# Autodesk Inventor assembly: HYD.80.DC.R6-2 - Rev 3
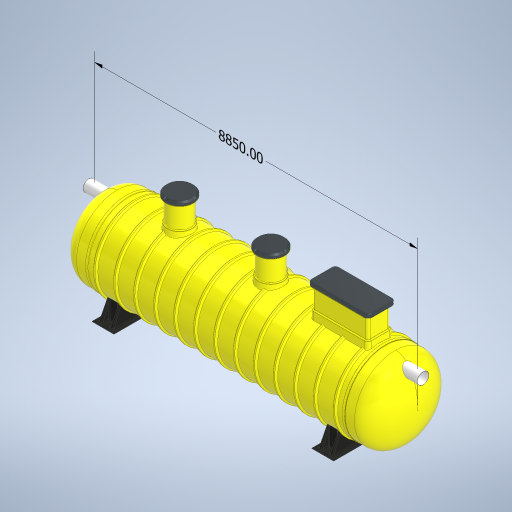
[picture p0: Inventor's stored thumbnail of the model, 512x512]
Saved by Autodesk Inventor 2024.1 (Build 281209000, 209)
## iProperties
Created: 2023-08
Part Number: HYD.80.DC.R6-2 - Rev 3
Document SubType Name: Assembly
Designer: macga
Author: macga
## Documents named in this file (44)
- D:\$ Protector Vault\Workspace\Automation Files\1. Protector Stardard Products\HydroProtectors\FAMILY\HYD.80 - Vernon\HYD.80.DC.R6-2 - Rev 3.iam
- D:\$ Protector Vault\Workspace\1. Protector Stardard Products\HydroProtectors\FAMILY\HORIZONTAL TANK - IPART\HORIZONTAL TANK - IPART.ipt
- D:\$ Protector Vault\Workspace\1. Protector Stardard Products\HydroProtectors\FAMILY\DOME - IPART\DOME - IPART.ipt
- D:\$ Protector Vault\Workspace\1. Protector Stardard Products\HydroProtectors\FAMILY\FOOT - IPART\FRP Foot - IPART.ipt
- D:\$ Protector Vault\Workspace\1. Protector Stardard Products\HydroProtectors\FAMILY\ACDTUBE - IPART\ACDTUBE - IPART.ipt
- D:\$ Protector Vault\Workspace\1. Protector Stardard Products\HydroProtectors\FAMILY\ACD FLOAT VALVE - IPART\ACD.FloatValve - IASSY.iam
- D:\$ Protector Vault\Workspace\1. Protector Stardard Products\HydroProtectors\FAMILY\SU.600Dia Manway Adaptor - IPART\SU.MWA.HS.6R - IPART.ipt
- D:\$ Protector Vault\Workspace\1. Protector Stardard Products\HydroProtectors\FAMILY\WIN.600mmDiaManwayRiser - IPART\600mmDia Manway Riser.ipt
- D:\$ Protector Vault\Workspace\1. Protector Stardard Products\HydroProtectors\Automation Files\600mmDia Manway Cover.ipt
- D:\$ Protector Vault\Workspace\1. Protector Stardard Products\HydroProtectors\FAMILY\OUTLET ELBOW - IPART\OUTLET ELBOW - IPART.ipt
- D:\$ Protector Vault\Workspace\1. Protector Stardard Products\HydroProtectors\Coalescer Guide Rail.ipt
- D:\$ Protector Vault\Workspace\1. Protector Stardard Products\HydroProtectors\ISO 4065 Pipe DN315x2.5xS63 - 1365.ipt
- D:\$ Protector Vault\Workspace\1. Protector Stardard Products\HydroProtectors\FAMILY\INLET PIPE ELBOW- IPART\INLET PIPE ELBOW- IPART\InletPipeElbow.300D.ipt
- D:\$ Protector Vault\Workspace\1. Protector Stardard Products\HydroProtectors\FAMILY\INLET PIPE ELBOW- IPART\INLET PIPE ELBOW- IPART.ipt
- D:\$ Protector Vault\Workspace\1. Protector Stardard Products\HydroProtectors\Upper Guide Rai Braket.ipt
- D:\$ Protector Vault\Workspace\1. Protector Stardard Products\Standard Components\Flanged Vent.ipt
- D:\$ Protector Vault\Workspace\1. Protector Stardard Products\HydroProtectors\HYD Oil Probe\Oil Probe Assembly.iam
- D:\$ Protector Vault\Workspace\1. Protector Stardard Products\HydroProtectors\FAMILY\DOME - IPART\DOME - IPART\SU.DOME.2200-10.ipt
- D:\$ Protector Vault\Workspace\1. Protector Stardard Products\HydroProtectors\FAMILY\FOOT - IPART\FRP Foot - IPART\SU.HS.FOOT.2200.ipt
- D:\$ Protector Vault\Workspace\1. Protector Stardard Products\HydroProtectors\FAMILY\HYD.BAFFLE - IPART\SU.BAFFLE.2200\SU.BAFFLE.2200.ipt
- D:\$ Protector Vault\Workspace\1. Protector Stardard Products\HydroProtectors\FAMILY\HYD.BAFFLE - IPART\SU.BAFFLE.2200.ipt
- D:\$ Protector Vault\Workspace\1. Protector Stardard Products\HydroProtectors\FAMILY\SU.600Dia Manway Adaptor - IPART\Horizontal 600mmDia Manway Adaptor (FLANGED) SU.MWA.HS.6R-1850-1850\SU.MWA.HS.6R-2200.ipt
- D:\$ Protector Vault\Workspace\1. Protector Stardard Products\HydroProtectors\FAMILY\ACD Base - IPART\SU.ACDBASE.2200\SU.ACDBASE.2200-450ACDFV.ipt
- D:\$ Protector Vault\Workspace\1. Protector Stardard Products\HydroProtectors\FAMILY\ACD Base - IPART\SU.ACDBASE.2200.ipt
- D:\$ Protector Vault\Workspace\1. Protector Stardard Products\HydroProtectors\HYD.70 300 Outlet Vertical.ipt
- D:\$ Protector Vault\Workspace\1. Protector Stardard Products\HydroProtectors\FAMILY\ACDTUBE - IPART\ACDTUBE - IPART\ACDTUBE.450-1846.ipt
- D:\$ Protector Vault\Workspace\1. Protector Stardard Products\HydroProtectors\FAMILY\ACD FLOAT VALVE - IPART\ACD.FloatValve - IASSY\ACD.FVALVE.450.ASSY.iam
- D:\$ Protector Vault\Workspace\1. Protector Stardard Products\HydroProtectors\FAMILY\OUTLET ELBOW - IPART\OUTLET ELBOW - IPART\OutletPipeElbow.300D-100DCoupling.ipt
- D:\$ Protector Vault\Workspace\1. Protector Stardard Products\Xtremeprotector\Vault\Chain.ipt
- D:\$ Protector Vault\Workspace\1. Protector Stardard Products\Xtremeprotector\Vault\Lifting Eye.ipt
- D:\$ Protector Vault\Workspace\1. Protector Stardard Products\HydroProtectors\FAMILY\Coalescer Guide Rail-018.ipt
- D:\$ Protector Vault\Workspace\1. Protector Stardard Products\HydroProtectors\FAMILY\Coalescer Guide Rail-019.ipt
- D:\$ Protector Vault\Workspace\Automation Files\1. Protector Stardard Products\HydroProtectors\FAMILY\CF.BASE - IPART\CF BASE DUAL - IPART\SU.CFBASE.2200.DUAL.ipt
- D:\$ Protector Vault\Workspace\1. Protector Stardard Products\HydroProtectors\FAMILY\HORIZONTAL TANK - IPART\HORIZONTAL TANK - IPART\WIN.HB.2200x7090L-10.ipt
- D:\$ Protector Vault\Workspace\Automation Files\1. Protector Stardard Products\HydroProtectors\FAMILY\CF.BASE - IPART\CF BASE DUAL - IPART\SU.CFBASE.2200.DUAL\SU.CFBASE.2200.B1.2-R6-OP.300.ipt
- D:\$ Protector Vault\Workspace\1. Protector Stardard Products\HydroProtectors\FAMILY\COALESCER FILTER - IPART\CF-R6.iam
- D:\$ Protector Vault\Workspace\1. Protector Stardard Products\Xtremeprotector\Vault\Chain\Chain-37.ipt
- D:\$ Protector Vault\Workspace\1. Protector Stardard Products\HydroProtectors\FAMILY\SU.600X1500ManwayRiserAdaptor - IPART\600x1500mm Manway Adaptor - IPART.ipt
- D:\$ Protector Vault\Workspace\1. Protector Stardard Products\HydroProtectors\FAMILY\SU.600X1500ManwayRiserAdaptor - IPART\600x1500mm Manway Adaptor - IPART\SU.MRADAPTOR.2200.600Lx1500W.ipt
- D:\$ Protector Vault\Workspace\1. Protector Stardard Products\HydroProtectors\Automation Files\Access Risers\600x1500 Manway Riser.ipt
- D:\$ Protector Vault\Workspace\1. Protector Stardard Products\Standard Components\600x1500 Manway Cover ST\600x1500 Manway Cover Class D ST-02.ipt
- D:\$ Protector Vault\Workspace\1. Protector Stardard Products\Standard Components\600x1500 Manway Cover ST.ipt
- D:\$ Protector Vault\Workspace\1. Protector Stardard Products\HydroProtectors\FAMILY\WIN.600mmDiaManwayRiser - IPART\600mmDia Manway Riser\SU.600mmDia.ManwayRiser.700-10.ipt
- D:\$ Protector Vault\Workspace\1. Protector Stardard Products\Trade Waste Sampling Point Assembly 300 for 2200 Tank.iam
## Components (39 placed, 27 different names)
1. WIN.HB.2200x7090L-10:1
2. SU.DOME.2200-10:1 — Mate:1, Mate:3, Mate:56, Mate:78
3. ISO 4065 Pipe DN315x2.5xS63 - 1365:2 — Mate:56, Mate:57, Mate:84, Mate:103
4. InletPipeElbow.300D:1 — Mate:57, Mate:103
5. SU.DOME.2200-10:2 — Mate:2, Mate:4
6. SU.HS.FOOT.2200:1 — Mate:74, Mate:75
7. SU.HS.FOOT.2200:2 — Mate:76, Mate:77
8. SU.BAFFLE.2200:1 — Mate:9, Mate:78, Mate:97
9. SU.ACDBASE.2200-450ACDFV:1 — Mate:11, Mate:14, Mate:97, Mate:98
10. ACDTUBE.450-1846:1 — Mate:14, Mate:15, Mate:98, Mate:99
11. ACD.FVALVE.450.ASSY:1 [sub-assembly] — Mate:15
12. SU.MWA.HS.6R-2200:2 — Mate:39, Mate:40, Mate:41, Mate:68, Mate:69, Tangent:2, Mate:99, Mate:100
13. SU.600mmDia.ManwayRiser.700-10:1 — Mate:30, Mate:31, Mate:40, Mate:41
14. 600mmDia Manway Cover:2 — Mate:30, Mate:31, Angle:2, Flush:13, Flush:14
15. Flanged Vent:2 — Mate:68, Mate:69
16. SU.MWA.HS.6R-2200:3 — Mate:43, Mate:44, Mate:45, Mate:66, Mate:67, Mate:100, Mate:105
17. SU.600mmDia.ManwayRiser.700-10:2 — Mate:44, Mate:32, Mate:33, Mate:45
18. Flanged Vent:1 — Mate:66, Mate:67
19. 600mmDia Manway Cover:1 — Mate:32, Mate:33, Flush:14
20. Oil Probe Assembly:1 [sub-assembly] — Mate:105
21. SU.CFBASE.2200.B1.2-R6-OP.300:1
22. CF-R6:1 [sub-assembly] — Mate:18, Mate:19, Mate:93, Tangent:3
23. CF-R6:2 [sub-assembly] — Mate:20, Mate:21, Mate:94, Tangent:5
24. HYD.70 300 Outlet Vertical:1 — Mate:35, Mate:37, Mate:102
25. OutletPipeElbow.300D-100DCoupling:2 — Mate:37, Mate:54, Mate:102, Mate:55
26. ISO 4065 Pipe DN315x2.5xS63 - 1365:1 — Mate:54, Mate:55, Mate:84, Mate:115, Mate:116
27. Coalescer Guide Rail-018:1 — Mate:47, Mate:49, Mate:62, Mate:63, Flush:5, Flush:10
28. Coalescer Guide Rail-019:2 — Mate:50, Mate:64, Mate:65, Flush:6, Flush:10
29. Upper Guide Rai Braket:1 — Mate:62, Mate:63, Flush:5
30. Upper Guide Rai Braket:2 — Mate:64, Mate:65, Flush:6
31. SU.MRADAPTOR.2200.600Lx1500W:1 — Mate:106, Mate:107, Mate:108
32. 600x1500 Manway Riser:1 — Mate:106, Mate:107, Mate:108, Mate:109, Flush:11, Flush:12, Mate:110, Mate:111, Mate:112, Mate:113, Mate:114
33. 600x1500 Manway Cover Class D ST-02:1 — Mate:109, Flush:11, Flush:12, Flush:13
34. Flanged Vent:3
35. Lifting Eye:1 — Tangent:4, Mate:110, Mate:112
36. Lifting Eye:2 — Tangent:6, Mate:111, Mate:113, Mate:114
37. Chain-37:1 — Mate:93, Tangent:3, Tangent:4
38. Chain-37:2 — Mate:94, Tangent:5, Tangent:6
39. Trade Waste Sampling Point Assembly 300 for 2200 Tank:1 [sub-assembly] — Mate:115, Mate:116
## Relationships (78: Mate 65, Flush 7, Tangent 5, Angle 1)
- Mate:1: SU.DOME.2200-10:1
- Mate:2: SU.DOME.2200-10:2
- Mate:3: SU.DOME.2200-10:1
- Mate:4: SU.DOME.2200-10:2
- Mate:9: SU.BAFFLE.2200:1
- Mate:11: SU.ACDBASE.2200-450ACDFV:1
- Mate:14: SU.ACDBASE.2200-450ACDFV:1 ↔ ACDTUBE.450-1846:1
- Mate:15: ACDTUBE.450-1846:1 ↔ ACD.FVALVE.450.ASSY:1
- Mate:18: CF-R6:1
- Mate:19: CF-R6:1
- Mate:20: CF-R6:2
- Mate:21: CF-R6:2
- Mate:30: SU.600mmDia.ManwayRiser.700-10:1 ↔ 600mmDia Manway Cover:2
- Mate:31: SU.600mmDia.ManwayRiser.700-10:1 ↔ 600mmDia Manway Cover:2
- Mate:44: SU.MWA.HS.6R-2200:3 ↔ SU.600mmDia.ManwayRiser.700-10:2
- Mate:32: SU.600mmDia.ManwayRiser.700-10:2 ↔ 600mmDia Manway Cover:1
- Mate:33: SU.600mmDia.ManwayRiser.700-10:2 ↔ 600mmDia Manway Cover:1
- Mate:35: HYD.70 300 Outlet Vertical:1
- Mate:37: HYD.70 300 Outlet Vertical:1 ↔ OutletPipeElbow.300D-100DCoupling:2
- Mate:39: SU.MWA.HS.6R-2200:2
- Mate:40: SU.MWA.HS.6R-2200:2 ↔ SU.600mmDia.ManwayRiser.700-10:1
- Mate:41: SU.MWA.HS.6R-2200:2 ↔ SU.600mmDia.ManwayRiser.700-10:1
- Mate:43: SU.MWA.HS.6R-2200:3
- Mate:45: SU.MWA.HS.6R-2200:3 ↔ SU.600mmDia.ManwayRiser.700-10:2
- Mate:47: Coalescer Guide Rail-018:1
- Mate:49: Coalescer Guide Rail-018:1
- Mate:50: Coalescer Guide Rail-019:2
- Mate:54: OutletPipeElbow.300D-100DCoupling:2 ↔ ISO 4065 Pipe DN315x2.5xS63 - 1365:1
- Mate:55: OutletPipeElbow.300D-100DCoupling:2 ↔ ISO 4065 Pipe DN315x2.5xS63 - 1365:1
- Mate:56: SU.DOME.2200-10:1 ↔ ISO 4065 Pipe DN315x2.5xS63 - 1365:2
- Mate:57: ISO 4065 Pipe DN315x2.5xS63 - 1365:2 ↔ InletPipeElbow.300D:1
- Mate:62: Coalescer Guide Rail-018:1 ↔ Upper Guide Rai Braket:1
- Mate:63: Coalescer Guide Rail-018:1 ↔ Upper Guide Rai Braket:1
- Flush:5: Coalescer Guide Rail-018:1 ↔ Upper Guide Rai Braket:1
- Mate:64: Coalescer Guide Rail-019:2 ↔ Upper Guide Rai Braket:2
- Mate:65: Coalescer Guide Rail-019:2 ↔ Upper Guide Rai Braket:2
- Flush:6: Coalescer Guide Rail-019:2 ↔ Upper Guide Rai Braket:2
- Mate:66: SU.MWA.HS.6R-2200:3 ↔ Flanged Vent:1
- Mate:67: SU.MWA.HS.6R-2200:3 ↔ Flanged Vent:1
- Mate:68: SU.MWA.HS.6R-2200:2 ↔ Flanged Vent:2
- Mate:69: SU.MWA.HS.6R-2200:2 ↔ Flanged Vent:2
- Angle:2: 600mmDia Manway Cover:2
- Tangent:2: SU.MWA.HS.6R-2200:2
- Mate:74: SU.HS.FOOT.2200:1
- Mate:75: SU.HS.FOOT.2200:1
- Mate:76: SU.HS.FOOT.2200:2
- Mate:77: SU.HS.FOOT.2200:2
- Mate:78: SU.DOME.2200-10:1 ↔ SU.BAFFLE.2200:1
- Mate:84: ISO 4065 Pipe DN315x2.5xS63 - 1365:2 ↔ ISO 4065 Pipe DN315x2.5xS63 - 1365:1
- Flush:10: Coalescer Guide Rail-018:1 ↔ Coalescer Guide Rail-019:2
- Mate:93: CF-R6:1 ↔ Chain-37:1
- Tangent:3: CF-R6:1 ↔ Chain-37:1
- Tangent:4: Lifting Eye:1 ↔ Chain-37:1
- Mate:94: CF-R6:2 ↔ Chain-37:2
- Tangent:5: CF-R6:2 ↔ Chain-37:2
- Tangent:6: Lifting Eye:2 ↔ Chain-37:2
- Mate:97: SU.BAFFLE.2200:1 ↔ SU.ACDBASE.2200-450ACDFV:1
- Mate:98: SU.ACDBASE.2200-450ACDFV:1 ↔ ACDTUBE.450-1846:1
- Mate:99: ACDTUBE.450-1846:1 ↔ SU.MWA.HS.6R-2200:2
- Mate:100: SU.MWA.HS.6R-2200:2 ↔ SU.MWA.HS.6R-2200:3
- Mate:105: SU.MWA.HS.6R-2200:3 ↔ Oil Probe Assembly:1
- Mate:102: HYD.70 300 Outlet Vertical:1 ↔ OutletPipeElbow.300D-100DCoupling:2
- Mate:103: ISO 4065 Pipe DN315x2.5xS63 - 1365:2 ↔ InletPipeElbow.300D:1
- Mate:106: SU.MRADAPTOR.2200.600Lx1500W:1 ↔ 600x1500 Manway Riser:1
- Mate:107: SU.MRADAPTOR.2200.600Lx1500W:1 ↔ 600x1500 Manway Riser:1
- Mate:108: SU.MRADAPTOR.2200.600Lx1500W:1 ↔ 600x1500 Manway Riser:1
- Mate:109: 600x1500 Manway Riser:1 ↔ 600x1500 Manway Cover Class D ST-02:1
- Flush:11: 600x1500 Manway Riser:1 ↔ 600x1500 Manway Cover Class D ST-02:1
- Flush:12: 600x1500 Manway Riser:1 ↔ 600x1500 Manway Cover Class D ST-02:1
- Mate:110: 600x1500 Manway Riser:1 ↔ Lifting Eye:1
- Mate:111: 600x1500 Manway Riser:1 ↔ Lifting Eye:2
- Mate:112: 600x1500 Manway Riser:1 ↔ Lifting Eye:1
- Mate:113: 600x1500 Manway Riser:1 ↔ Lifting Eye:2
- Mate:114: 600x1500 Manway Riser:1 ↔ Lifting Eye:2
- Flush:13: 600mmDia Manway Cover:2 ↔ 600x1500 Manway Cover Class D ST-02:1
- Flush:14: 600mmDia Manway Cover:2 ↔ 600mmDia Manway Cover:1
- Mate:115: ISO 4065 Pipe DN315x2.5xS63 - 1365:1 ↔ Trade Waste Sampling Point Assembly 300 for 2200 Tank:1
- Mate:116: ISO 4065 Pipe DN315x2.5xS63 - 1365:1 ↔ Trade Waste Sampling Point Assembly 300 for 2200 Tank:1
